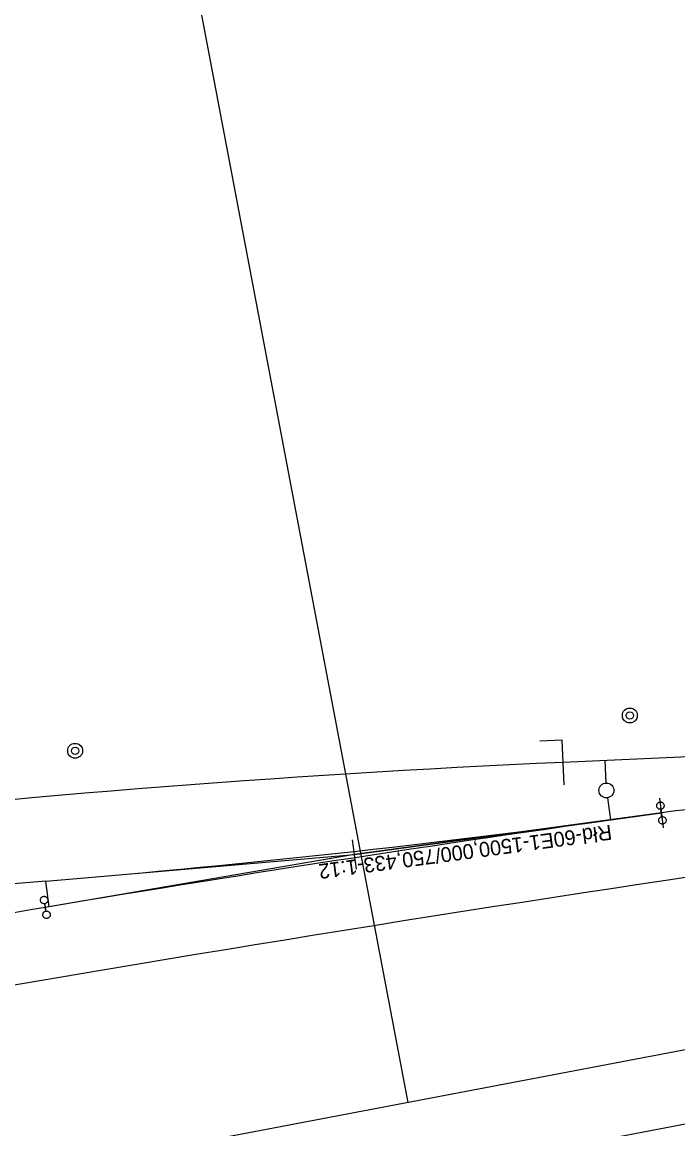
# Model space of a CAD drawing. Extents: x 6540402 to 6566579, y 5525343 to 5532423.
# Drawn here: x 6558170 to 6558214, y 5528818.6 to 5528892.8 of the extents above; entities that cross this region are included whole.
import ezdxf

# ---------------------------------------------------------------- set-up
doc = ezdxf.new("R2010")
doc.units = 0
for name, color, linetype in [('IR_ps_geometria', 7, 'Continuous'), ('TOR_PS_ODW-studnie betonowe', 7, 'Continuous'), ('TOR_PS_OPIS_T-opisy dodatkowe', 7, 'Continuous'), ('TOR_PS_OPIS_T-symbole geometrii', 7, 'Continuous'), ('TOR_PS_OPIS_T-ukresy', 7, 'Continuous'), ('TOR_PS_T-rozjazdy projektowane', 7, 'Continuous'), ('TOR_PS_T-tory projektowane', 7, 'Continuous')]:
    doc.layers.add(name, color=color, linetype=linetype)

msp = doc.modelspace()

# ---------------------------------------------------------------- linework, layer by layer
at = {"layer": 'IR_ps_geometria'}
for points in [[(6558212.92, 5528839.768), (6558212.955, 5528839.52), (6558212.987, 5528839.523), (6558213.02, 5528839.521), (6558213.052, 5528839.515), (6558213.083, 5528839.504), (6558213.112, 5528839.49), (6558213.14, 5528839.472), (6558213.164, 5528839.451), (6558213.186, 5528839.426), (6558213.205, 5528839.399), (6558213.219, 5528839.37), (6558213.23, 5528839.339), (6558213.237, 5528839.307), (6558213.239, 5528839.274), (6558213.237, 5528839.242), (6558213.231, 5528839.21), (6558213.221, 5528839.179), (6558213.206, 5528839.149), (6558213.188, 5528839.122), (6558213.167, 5528839.097), (6558213.143, 5528839.075), (6558213.115, 5528839.057), (6558213.086, 5528839.042), (6558213.055, 5528839.032), (6558213.023, 5528839.025), (6558212.991, 5528839.023), (6558212.958, 5528839.025), (6558212.926, 5528839.031), (6558212.895, 5528839.041), (6558212.865, 5528839.055), (6558212.838, 5528839.073), (6558212.813, 5528839.095), (6558212.792, 5528839.119), (6558212.773, 5528839.146), (6558212.759, 5528839.175), (6558212.748, 5528839.206), (6558212.741, 5528839.238), (6558212.739, 5528839.271), (6558212.741, 5528839.303), (6558212.747, 5528839.336), (6558212.757, 5528839.367), (6558212.772, 5528839.396), (6558212.79, 5528839.423), (6558212.811, 5528839.448), (6558212.835, 5528839.47), (6558212.862, 5528839.488), (6558212.892, 5528839.503), (6558212.923, 5528839.514), (6558212.955, 5528839.52), (6558212.886, 5528840.015), (6558212.853, 5528840.013), (6558212.821, 5528840.015), (6558212.788, 5528840.021), (6558212.757, 5528840.031), (6558212.728, 5528840.046), (6558212.701, 5528840.064), (6558212.676, 5528840.085), (6558212.654, 5528840.109), (6558212.636, 5528840.137), (6558212.621, 5528840.166), (6558212.61, 5528840.197), (6558212.604, 5528840.229), (6558212.601, 5528840.261), (6558212.603, 5528840.294), (6558212.609, 5528840.326), (6558212.62, 5528840.357), (6558212.634, 5528840.387), (6558212.652, 5528840.414), (6558212.673, 5528840.439), (6558212.698, 5528840.46), (6558212.725, 5528840.479), (6558212.754, 5528840.493), (6558212.785, 5528840.504), (6558212.817, 5528840.511), (6558212.85, 5528840.513), (6558212.882, 5528840.511), (6558212.914, 5528840.505), (6558212.945, 5528840.495), (6558212.975, 5528840.48), (6558213.002, 5528840.463), (6558213.027, 5528840.441), (6558213.049, 5528840.417), (6558213.067, 5528840.39), (6558213.082, 5528840.36), (6558213.092, 5528840.33), (6558213.099, 5528840.297), (6558213.101, 5528840.265), (6558213.099, 5528840.232), (6558213.093, 5528840.2), (6558213.083, 5528840.169), (6558213.069, 5528840.14), (6558213.051, 5528840.112), (6558213.029, 5528840.088), (6558213.005, 5528840.066), (6558212.978, 5528840.047), (6558212.949, 5528840.033), (6558212.918, 5528840.022), (6558212.886, 5528840.015)], [(6558212.92, 5528839.768), (6558212.955, 5528839.52), (6558212.987, 5528839.523), (6558213.02, 5528839.521), (6558213.052, 5528839.515), (6558213.083, 5528839.504), (6558213.112, 5528839.49), (6558213.14, 5528839.472), (6558213.164, 5528839.451), (6558213.186, 5528839.426), (6558213.205, 5528839.399), (6558213.219, 5528839.37), (6558213.23, 5528839.339), (6558213.237, 5528839.307), (6558213.239, 5528839.274), (6558213.237, 5528839.242), (6558213.231, 5528839.21), (6558213.221, 5528839.179), (6558213.206, 5528839.149), (6558213.188, 5528839.122), (6558213.167, 5528839.097), (6558213.143, 5528839.075), (6558213.115, 5528839.057), (6558213.086, 5528839.042), (6558213.055, 5528839.032), (6558213.023, 5528839.025), (6558212.991, 5528839.023), (6558212.958, 5528839.025), (6558212.926, 5528839.031), (6558212.895, 5528839.041), (6558212.865, 5528839.055), (6558212.838, 5528839.073), (6558212.813, 5528839.095), (6558212.792, 5528839.119), (6558212.773, 5528839.146), (6558212.759, 5528839.175), (6558212.748, 5528839.206), (6558212.741, 5528839.238), (6558212.739, 5528839.271), (6558212.741, 5528839.303), (6558212.747, 5528839.336), (6558212.757, 5528839.367), (6558212.772, 5528839.396), (6558212.79, 5528839.423), (6558212.811, 5528839.448), (6558212.835, 5528839.47), (6558212.862, 5528839.488), (6558212.892, 5528839.503), (6558212.923, 5528839.514), (6558212.955, 5528839.52), (6558212.886, 5528840.015), (6558212.853, 5528840.013), (6558212.821, 5528840.015), (6558212.788, 5528840.021), (6558212.757, 5528840.031), (6558212.728, 5528840.046), (6558212.701, 5528840.064), (6558212.676, 5528840.085), (6558212.654, 5528840.109), (6558212.636, 5528840.137), (6558212.621, 5528840.166), (6558212.61, 5528840.197), (6558212.604, 5528840.229), (6558212.601, 5528840.261), (6558212.603, 5528840.294), (6558212.609, 5528840.326), (6558212.62, 5528840.357), (6558212.634, 5528840.387), (6558212.652, 5528840.414), (6558212.673, 5528840.439), (6558212.698, 5528840.46), (6558212.725, 5528840.479), (6558212.754, 5528840.493), (6558212.785, 5528840.504), (6558212.817, 5528840.511), (6558212.85, 5528840.513), (6558212.882, 5528840.511), (6558212.914, 5528840.505), (6558212.945, 5528840.495), (6558212.975, 5528840.48), (6558213.002, 5528840.463), (6558213.027, 5528840.441), (6558213.049, 5528840.417), (6558213.067, 5528840.39), (6558213.082, 5528840.36), (6558213.092, 5528840.33), (6558213.099, 5528840.297), (6558213.101, 5528840.265), (6558213.099, 5528840.232), (6558213.093, 5528840.2), (6558213.083, 5528840.169), (6558213.069, 5528840.14), (6558213.051, 5528840.112), (6558213.029, 5528840.088), (6558213.005, 5528840.066), (6558212.978, 5528840.047), (6558212.949, 5528840.033), (6558212.918, 5528840.022), (6558212.886, 5528840.015)], [(6558212.92, 5528839.768), (6558212.955, 5528839.52), (6558212.987, 5528839.523), (6558213.02, 5528839.521), (6558213.052, 5528839.515), (6558213.083, 5528839.504), (6558213.112, 5528839.49), (6558213.14, 5528839.472), (6558213.164, 5528839.451), (6558213.186, 5528839.426), (6558213.205, 5528839.399), (6558213.219, 5528839.37), (6558213.23, 5528839.339), (6558213.237, 5528839.307), (6558213.239, 5528839.274), (6558213.237, 5528839.242), (6558213.231, 5528839.21), (6558213.221, 5528839.179), (6558213.206, 5528839.149), (6558213.188, 5528839.122), (6558213.167, 5528839.097), (6558213.143, 5528839.075), (6558213.115, 5528839.057), (6558213.086, 5528839.042), (6558213.055, 5528839.032), (6558213.023, 5528839.025), (6558212.991, 5528839.023), (6558212.958, 5528839.025), (6558212.926, 5528839.031), (6558212.895, 5528839.041), (6558212.865, 5528839.055), (6558212.838, 5528839.073), (6558212.813, 5528839.095), (6558212.792, 5528839.119), (6558212.773, 5528839.146), (6558212.759, 5528839.175), (6558212.748, 5528839.206), (6558212.741, 5528839.238), (6558212.739, 5528839.271), (6558212.741, 5528839.303), (6558212.747, 5528839.336), (6558212.757, 5528839.367), (6558212.772, 5528839.396), (6558212.79, 5528839.423), (6558212.811, 5528839.448), (6558212.835, 5528839.47), (6558212.862, 5528839.488), (6558212.892, 5528839.503), (6558212.923, 5528839.514), (6558212.955, 5528839.52), (6558212.886, 5528840.015), (6558212.853, 5528840.013), (6558212.821, 5528840.015), (6558212.788, 5528840.021), (6558212.757, 5528840.031), (6558212.728, 5528840.046), (6558212.701, 5528840.064), (6558212.676, 5528840.085), (6558212.654, 5528840.109), (6558212.636, 5528840.137), (6558212.621, 5528840.166), (6558212.61, 5528840.197), (6558212.604, 5528840.229), (6558212.601, 5528840.261), (6558212.603, 5528840.294), (6558212.609, 5528840.326), (6558212.62, 5528840.357), (6558212.634, 5528840.387), (6558212.652, 5528840.414), (6558212.673, 5528840.439), (6558212.698, 5528840.46), (6558212.725, 5528840.479), (6558212.754, 5528840.493), (6558212.785, 5528840.504), (6558212.817, 5528840.511), (6558212.85, 5528840.513), (6558212.882, 5528840.511), (6558212.914, 5528840.505), (6558212.945, 5528840.495), (6558212.975, 5528840.48), (6558213.002, 5528840.463), (6558213.027, 5528840.441), (6558213.049, 5528840.417), (6558213.067, 5528840.39), (6558213.082, 5528840.36), (6558213.092, 5528840.33), (6558213.099, 5528840.297), (6558213.101, 5528840.265), (6558213.099, 5528840.232), (6558213.093, 5528840.2), (6558213.083, 5528840.169), (6558213.069, 5528840.14), (6558213.051, 5528840.112), (6558213.029, 5528840.088), (6558213.005, 5528840.066), (6558212.978, 5528840.047), (6558212.949, 5528840.033), (6558212.918, 5528840.022), (6558212.886, 5528840.015)], [(6558171.549, 5528833.433), (6558171.59, 5528833.186), (6558171.623, 5528833.189), (6558171.655, 5528833.188), (6558171.688, 5528833.183), (6558171.719, 5528833.174), (6558171.749, 5528833.16), (6558171.777, 5528833.143), (6558171.802, 5528833.122), (6558171.824, 5528833.098), (6558171.843, 5528833.072), (6558171.859, 5528833.043), (6558171.87, 5528833.013), (6558171.878, 5528832.981), (6558171.881, 5528832.948), (6558171.88, 5528832.915), (6558171.875, 5528832.883), (6558171.866, 5528832.852), (6558171.852, 5528832.822), (6558171.835, 5528832.794), (6558171.814, 5528832.769), (6558171.79, 5528832.746), (6558171.764, 5528832.727), (6558171.735, 5528832.712), (6558171.704, 5528832.7), (6558171.673, 5528832.693), (6558171.64, 5528832.69), (6558171.607, 5528832.691), (6558171.575, 5528832.696), (6558171.544, 5528832.705), (6558171.514, 5528832.719), (6558171.486, 5528832.736), (6558171.461, 5528832.757), (6558171.438, 5528832.78), (6558171.419, 5528832.807), (6558171.404, 5528832.836), (6558171.392, 5528832.866), (6558171.385, 5528832.898), (6558171.382, 5528832.931), (6558171.383, 5528832.963), (6558171.388, 5528832.996), (6558171.397, 5528833.027), (6558171.411, 5528833.057), (6558171.428, 5528833.085), (6558171.449, 5528833.11), (6558171.472, 5528833.132), (6558171.499, 5528833.151), (6558171.528, 5528833.167), (6558171.558, 5528833.178), (6558171.59, 5528833.186), (6558171.508, 5528833.679), (6558171.475, 5528833.676), (6558171.442, 5528833.677), (6558171.41, 5528833.682), (6558171.379, 5528833.691), (6558171.349, 5528833.705), (6558171.321, 5528833.722), (6558171.296, 5528833.743), (6558171.273, 5528833.767), (6558171.254, 5528833.793), (6558171.239, 5528833.822), (6558171.227, 5528833.853), (6558171.22, 5528833.884), (6558171.216, 5528833.917), (6558171.217, 5528833.95), (6558171.223, 5528833.982), (6558171.232, 5528834.013), (6558171.245, 5528834.043), (6558171.263, 5528834.071), (6558171.283, 5528834.096), (6558171.307, 5528834.119), (6558171.334, 5528834.138), (6558171.363, 5528834.153), (6558171.393, 5528834.165), (6558171.425, 5528834.172), (6558171.457, 5528834.176), (6558171.49, 5528834.175), (6558171.522, 5528834.169), (6558171.554, 5528834.16), (6558171.584, 5528834.146), (6558171.611, 5528834.129), (6558171.637, 5528834.109), (6558171.659, 5528834.085), (6558171.678, 5528834.058), (6558171.694, 5528834.029), (6558171.705, 5528833.999), (6558171.713, 5528833.967), (6558171.716, 5528833.934), (6558171.715, 5528833.902), (6558171.71, 5528833.869), (6558171.7, 5528833.838), (6558171.687, 5528833.808), (6558171.67, 5528833.781), (6558171.649, 5528833.755), (6558171.625, 5528833.733), (6558171.599, 5528833.714), (6558171.57, 5528833.698), (6558171.539, 5528833.687), (6558171.508, 5528833.679)], [(6558171.549, 5528833.433), (6558171.59, 5528833.186), (6558171.623, 5528833.189), (6558171.655, 5528833.188), (6558171.688, 5528833.183), (6558171.719, 5528833.174), (6558171.749, 5528833.16), (6558171.777, 5528833.143), (6558171.802, 5528833.122), (6558171.824, 5528833.098), (6558171.843, 5528833.072), (6558171.859, 5528833.043), (6558171.87, 5528833.013), (6558171.878, 5528832.981), (6558171.881, 5528832.948), (6558171.88, 5528832.915), (6558171.875, 5528832.883), (6558171.866, 5528832.852), (6558171.852, 5528832.822), (6558171.835, 5528832.794), (6558171.814, 5528832.769), (6558171.79, 5528832.746), (6558171.764, 5528832.727), (6558171.735, 5528832.712), (6558171.704, 5528832.7), (6558171.673, 5528832.693), (6558171.64, 5528832.69), (6558171.607, 5528832.691), (6558171.575, 5528832.696), (6558171.544, 5528832.705), (6558171.514, 5528832.719), (6558171.486, 5528832.736), (6558171.461, 5528832.757), (6558171.438, 5528832.78), (6558171.419, 5528832.807), (6558171.404, 5528832.836), (6558171.392, 5528832.866), (6558171.385, 5528832.898), (6558171.382, 5528832.931), (6558171.383, 5528832.963), (6558171.388, 5528832.996), (6558171.397, 5528833.027), (6558171.411, 5528833.057), (6558171.428, 5528833.085), (6558171.449, 5528833.11), (6558171.472, 5528833.132), (6558171.499, 5528833.151), (6558171.528, 5528833.167), (6558171.558, 5528833.178), (6558171.59, 5528833.186), (6558171.508, 5528833.679), (6558171.475, 5528833.676), (6558171.442, 5528833.677), (6558171.41, 5528833.682), (6558171.379, 5528833.691), (6558171.349, 5528833.705), (6558171.321, 5528833.722), (6558171.296, 5528833.743), (6558171.273, 5528833.767), (6558171.254, 5528833.793), (6558171.239, 5528833.822), (6558171.227, 5528833.853), (6558171.22, 5528833.884), (6558171.216, 5528833.917), (6558171.217, 5528833.95), (6558171.223, 5528833.982), (6558171.232, 5528834.013), (6558171.245, 5528834.043), (6558171.263, 5528834.071), (6558171.283, 5528834.096), (6558171.307, 5528834.119), (6558171.334, 5528834.138), (6558171.363, 5528834.153), (6558171.393, 5528834.165), (6558171.425, 5528834.172), (6558171.457, 5528834.176), (6558171.49, 5528834.175), (6558171.522, 5528834.169), (6558171.554, 5528834.16), (6558171.584, 5528834.146), (6558171.611, 5528834.129), (6558171.637, 5528834.109), (6558171.659, 5528834.085), (6558171.678, 5528834.058), (6558171.694, 5528834.029), (6558171.705, 5528833.999), (6558171.713, 5528833.967), (6558171.716, 5528833.934), (6558171.715, 5528833.902), (6558171.71, 5528833.869), (6558171.7, 5528833.838), (6558171.687, 5528833.808), (6558171.67, 5528833.781), (6558171.649, 5528833.755), (6558171.625, 5528833.733), (6558171.599, 5528833.714), (6558171.57, 5528833.698), (6558171.539, 5528833.687), (6558171.508, 5528833.679)], [(6558171.549, 5528833.433), (6558171.59, 5528833.186), (6558171.623, 5528833.189), (6558171.655, 5528833.188), (6558171.688, 5528833.183), (6558171.719, 5528833.174), (6558171.749, 5528833.16), (6558171.777, 5528833.143), (6558171.802, 5528833.122), (6558171.824, 5528833.098), (6558171.843, 5528833.072), (6558171.859, 5528833.043), (6558171.87, 5528833.013), (6558171.878, 5528832.981), (6558171.881, 5528832.948), (6558171.88, 5528832.915), (6558171.875, 5528832.883), (6558171.866, 5528832.852), (6558171.852, 5528832.822), (6558171.835, 5528832.794), (6558171.814, 5528832.769), (6558171.79, 5528832.746), (6558171.764, 5528832.727), (6558171.735, 5528832.712), (6558171.704, 5528832.7), (6558171.673, 5528832.693), (6558171.64, 5528832.69), (6558171.607, 5528832.691), (6558171.575, 5528832.696), (6558171.544, 5528832.705), (6558171.514, 5528832.719), (6558171.486, 5528832.736), (6558171.461, 5528832.757), (6558171.438, 5528832.78), (6558171.419, 5528832.807), (6558171.404, 5528832.836), (6558171.392, 5528832.866), (6558171.385, 5528832.898), (6558171.382, 5528832.931), (6558171.383, 5528832.963), (6558171.388, 5528832.996), (6558171.397, 5528833.027), (6558171.411, 5528833.057), (6558171.428, 5528833.085), (6558171.449, 5528833.11), (6558171.472, 5528833.132), (6558171.499, 5528833.151), (6558171.528, 5528833.167), (6558171.558, 5528833.178), (6558171.59, 5528833.186), (6558171.508, 5528833.679), (6558171.475, 5528833.676), (6558171.442, 5528833.677), (6558171.41, 5528833.682), (6558171.379, 5528833.691), (6558171.349, 5528833.705), (6558171.321, 5528833.722), (6558171.296, 5528833.743), (6558171.273, 5528833.767), (6558171.254, 5528833.793), (6558171.239, 5528833.822), (6558171.227, 5528833.853), (6558171.22, 5528833.884), (6558171.216, 5528833.917), (6558171.217, 5528833.95), (6558171.223, 5528833.982), (6558171.232, 5528834.013), (6558171.245, 5528834.043), (6558171.263, 5528834.071), (6558171.283, 5528834.096), (6558171.307, 5528834.119), (6558171.334, 5528834.138), (6558171.363, 5528834.153), (6558171.393, 5528834.165), (6558171.425, 5528834.172), (6558171.457, 5528834.176), (6558171.49, 5528834.175), (6558171.522, 5528834.169), (6558171.554, 5528834.16), (6558171.584, 5528834.146), (6558171.611, 5528834.129), (6558171.637, 5528834.109), (6558171.659, 5528834.085), (6558171.678, 5528834.058), (6558171.694, 5528834.029), (6558171.705, 5528833.999), (6558171.713, 5528833.967), (6558171.716, 5528833.934), (6558171.715, 5528833.902), (6558171.71, 5528833.869), (6558171.7, 5528833.838), (6558171.687, 5528833.808), (6558171.67, 5528833.781), (6558171.649, 5528833.755), (6558171.625, 5528833.733), (6558171.599, 5528833.714), (6558171.57, 5528833.698), (6558171.539, 5528833.687), (6558171.508, 5528833.679)]]:
    msp.add_lwpolyline(points, close=True, dxfattribs=at)
at = {"layer": 'TOR_PS_ODW-studnie betonowe'}
for centre, radius in [((6558210.8, 5528846.312), 0.5), ((6558210.8, 5528846.312), 0.25), ((6558173.554, 5528843.942), 0.5), ((6558173.554, 5528843.942), 0.25)]:
    msp.add_circle(centre, radius, dxfattribs=at)
at = {"layer": 'TOR_PS_OPIS_T-opisy dodatkowe'}
msp.add_line((6558052.508, 5529576.712), (6558195.882, 5528820.33), dxfattribs=at)
at = {"layer": 'TOR_PS_OPIS_T-symbole geometrii'}
for p, q in [((6558206.255, 5528844.662), (6558204.757, 5528844.595)), ((6558206.388, 5528841.664), (6558206.255, 5528844.662))]:
    msp.add_line(p, q, dxfattribs=at)
at = {"layer": 'TOR_PS_OPIS_T-ukresy'}
for p, q in [((6558209.205, 5528841.78), (6558209.138, 5528843.288)), ((6558209.294, 5528840.785), (6558209.493, 5528839.301))]:
    msp.add_line(p, q, dxfattribs=at)
msp.add_circle((6558209.228, 5528841.28), 0.5, dxfattribs=at)
at = {"layer": 'TOR_PS_T-rozjazdy projektowane'}
for p, q in [((6558212.793, 5528840.761), (6558213.047, 5528838.777)), ((6558192.437, 5528835.989), (6558192.183, 5528837.973))]:
    msp.add_line(p, q, dxfattribs=at)
msp.add_lwpolyline([(6558212.92, 5528839.769), (6558192.31, 5528836.981), (6558171.81, 5528833.476), (6558171.59, 5528835.192), (6558192.31, 5528836.981)], close=True, dxfattribs=at)
at = {"layer": 'TOR_PS_T-tory projektowane'}
for p, q in [((6558571.547, 5528891.538), (6557352.881, 5528660.537)), ((6558235.176, 5528844.447), (6558206.322, 5528843.163)), ((6558171.584, 5528835.191), (6558160.048, 5528834.237)), ((6558285.492, 5528832.329), (6557892.49, 5528757.834))]:
    msp.add_line(p, q, dxfattribs=at)
for centre, radius, start, end in [((6558241.925, 5528042.955), 801, 92.547544, 100.733241), ((6558419.265, 5527354.028), 1500, 97.311329, 97.906871), ((6558532.412, 5526709.067), 2150, 97.292803, 100.733239), ((6558419.265, 5527354.028), 1500, 97.906871, 99.505614), ((6558109.69, 5529583.067), 750.433, 274.731026, 277.90674), ((6558419.265, 5527354.028), 1500, 99.505614, 100.733384)]:
    msp.add_arc(centre, radius, start, end, dxfattribs=at)

# ---------------------------------------------------------------- texts
at = {"layer": 'TOR_PS_T-rozjazdy projektowane'}
msp.add_text('Rłd-60E1-1500,000/750,433-1:12', height=1, rotation=187.70174, dxfattribs=at).set_placement((6558209.522, 5528838.982))

doc.saveas('drawing.dxf')
